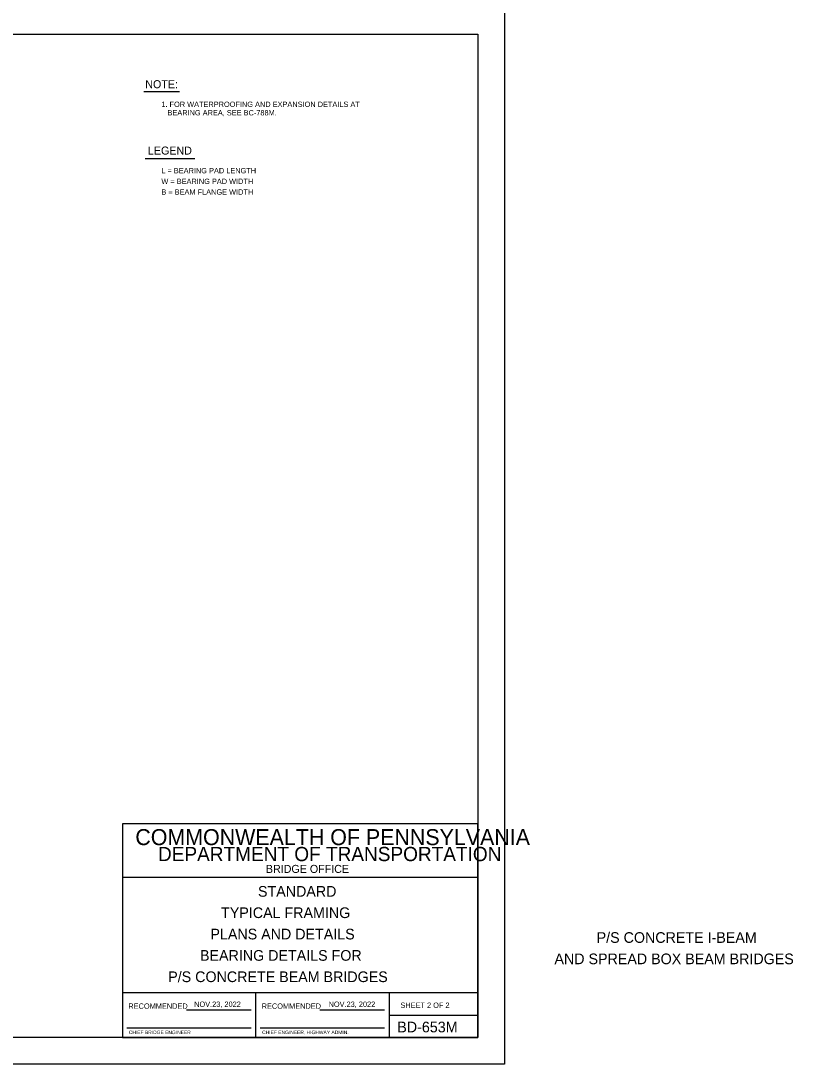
# Model space of a CAD drawing. Extents: x 639028 to 640031, y 298558 to 299746.
# Drawn here: x 639597 to 640031, y 298558 to 299145 of the extents above; entities that cross this region are included whole.
import ezdxf

# ---------------------------------------------------------------- set-up
doc = ezdxf.new("R2010")
doc.units = 0
for name, color, linetype in [('1', 7, 'Continuous'), ('DATES', 7, 'Continuous'), ('PLT-BNDY', 7, 'Continuous'), ('SIGNATORY TITLES', 7, 'Continuous')]:
    doc.layers.add(name, color=color, linetype=linetype)

msp = doc.modelspace()

# ---------------------------------------------------------------- linework, layer by layer
at = {"layer": '1'}
for p, q in [((639067.87, 299137.33), (639853.87, 299137.33)), ((639853.87, 299137.33), (639853.87, 298573.33)), ((639665.84, 299105.21), (639686.06, 299105.21)), ((639694.57, 299067.29), (639666.68, 299067.29)), ((639653.87, 298693.33), (639653.87, 298573.33)), ((639853.87, 298693.33), (639653.87, 298693.33)), ((639853.87, 298573.33), (639853.87, 298693.33)), ((639853.87, 298689.58), (639853.87, 298693.33)), ((639853.87, 298663.33), (639653.87, 298663.33)), ((639853.87, 298598.33), (639653.87, 298598.33)), ((639728.87, 298573.33), (639728.87, 298598.33)), ((639803.87, 298598.33), (639803.87, 298573.33)), ((639689.96, 298588.83), (639726.37, 298588.83)), ((639764.96, 298588.83), (639801.37, 298588.83)), ((639803.87, 298585.83), (639853.87, 298585.83)), ((639656.37, 298578.83), (639726.37, 298578.83)), ((639731.37, 298578.83), (639801.37, 298578.83)), ((639853.87, 298573.33), (639067.87, 298573.33)), ((639653.87, 298573.33), (639853.87, 298573.33))]:
    msp.add_line(p, q, dxfattribs=at)
at = {"layer": 'PLT-BNDY'}
msp.add_lwpolyline([(639027.87, 299152.33), (639868.87, 299152.33), (639868.87, 298558.33), (639027.87, 298558.33)], close=True, dxfattribs=at)

# ---------------------------------------------------------------- texts
at = {"layer": '1'}
for s, height, p in [('NOTE: ', 4.5, (639666.71, 299106.96)), ('1. FOR WATERPROOFING AND EXPANSION DETAILS AT', 3, (639675.77, 299096.43)), ('   BEARING AREA, SEE BC-788M.', 3, (639675.77, 299091.68)), ('LEGEND', 4.5, (639668.19, 299069.66)), ('L = BEARING PAD LENGTH', 3, (639675.77, 299059.12)), ('W = BEARING PAD WIDTH', 3, (639675.77, 299053.12)), ('B = BEAM FLANGE WIDTH', 3, (639675.77, 299047.12)), ('COMMONWEALTH OF PENNSYLVANIA', 9, (639661.12, 298681.45)), ('DEPARTMENT OF TRANSPORTATION', 8.0002, (639673.87, 298672.45)), ('BRIDGE OFFICE', 4.5, (639734.55, 298665.83)), ('STANDARD', 6, (639730.12, 298652.45)), ('TYPICAL FRAMING', 6, (639709.37, 298640.45)), ('PLANS AND DETAILS', 6, (639703.37, 298628.45)), ('P/S CONCRETE I-BEAM', 6, (639920.63, 298626.51)), ('BEARING DETAILS FOR', 6, (639697.51, 298616.45)), ('AND SPREAD BOX BEAM BRIDGES', 6, (639896.88, 298614.51)), ('P/S CONCRETE BEAM BRIDGES', 6, (639679.62, 298604.45)), ('RECOMMENDED', 3, (639657.2, 298589.45)), ('RECOMMENDED', 3, (639732.2, 298589.45)), ('SHEET 2 OF 2', 3, (639810.25, 298589.95)), ('BD-653M', 6, (639808.5, 298576.2))]:
    msp.add_text(s, height=height, dxfattribs=at).set_placement(p)
at = {"layer": 'DATES'}
for p in [(639694.21, 298590.51), (639769.83, 298590.51)]:
    msp.add_text('NOV.23, 2022', height=3, dxfattribs=at).set_placement(p)
at = {"layer": 'SIGNATORY TITLES'}
for s, p in [('CHIEF BRIDGE ENGINEER', (639657.46, 298575.2)), ('CHIEF ENGINEER, HIGHWAY ADMIN.', (639732.46, 298575.2))]:
    msp.add_text(s, height=2, dxfattribs=at).set_placement(p)

doc.saveas('drawing.dxf')
